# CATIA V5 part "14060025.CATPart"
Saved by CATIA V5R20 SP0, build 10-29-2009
Part number: 14060025
Definition: NONE
Nomenclature: 14060025
Source: Unknown
Description: 14060025
Bounding box of the stored display mesh (mm): x -12.5 to 50, y -44 to 33.913, z -34.1 to 34.1
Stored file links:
  C:\Users\Utente\Desktop\IO LAVORO\3D X SITO CF\X SITO\PLASTICA\RF2\14060025.CATPart
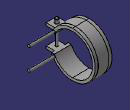
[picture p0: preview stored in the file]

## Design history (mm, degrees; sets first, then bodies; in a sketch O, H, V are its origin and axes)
Body1 "14060025" (main body)
  Solid1: solid without history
